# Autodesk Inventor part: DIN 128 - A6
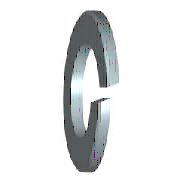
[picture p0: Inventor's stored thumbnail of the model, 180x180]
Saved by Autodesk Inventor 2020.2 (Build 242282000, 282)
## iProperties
Manager: www.cadconsulting.pl
Company: Fabian Stasiak CAD Consulting
Created: 2010-02
Part Number: DIN 128 - A6
Material: Stal, miękka
Description: Podkładka sprężysta
Document SubType Name: Modeling
Standard: DIN 128
Designer: F.Stasiak
Standard Revision: 1994
Standards Organization: DIN
Language: pl-PL
Size Designation: A6
Categories: <MemberInstance><Categories><Category DisplayName="Mocowania" InternalName="e4da775c-781d-43d5-af7c-5136215cf5a6" Mnemonic="FSTN"><Category DisplayName="Podkład
Density: 1 g/cm^3
Appearance: Metal-Stal
IsCustomPart: 0
Author: F.Stasiak
Subject: Zbiór ćwiczeń. Autodesk Inventor 2020. Kurs podstawowy
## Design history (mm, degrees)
sketch "Sketch1"
  geometry: C1 r 5.9 at (0, 0); C2 r 3.25 at (0, 0); 1 further point
  constraints: 2 centre point, 2 coincident
  dimensions: "d0" = 6.5 diameter of C2 (= SD1); "d1" = 11.8 diameter of C1 (= SD2)
extrude "Body" new body sketch "Sketch1" distance "d2" = 1.3 (= SD); taper "d3" = 0 deg
fillet "Fillet" dims "d13" = 0.3 (= R)
sketch "Sketch2"
  geometry: L1 (0, -3.25)-(0, 3.25) reference; L2 (1.3, 5.9)-(1.3, -5.9) reference; L3 (-1.2, 0)-(7.2, 0) reference; L4 (0, -0.26)-(1.3, 0.491); L5 (0, 0.26)-(1.3, 1.011)
  constraints: 4 end point, 4 point on line, 1 parallel
  dimensions: "d4" = 0.26 distance from line of L3 L4.start (= 0.2 x SD); "d5" = 0.26 distance from line of L3 L5.start (= 0.2 x SD); "d6" = 60 deg angle of L2 L4 (= FAWI)
extrude "Cut" cut sketch "Sketch2" stored distance "d7" = 1.3 (= SD); taper "d8" = 0 deg
workaxis "Work Axis1"
workplane "Work Plane1"
body "Solid1"
other parameters: "SD1" = 6.5 [user parameter; used in 1 equation term], "SD2" = 11.8 [user parameter; used in 1 equation term], "SD" = 1.3 [user parameter; used in 4 equation terms], "FAWI" = 60 deg [user parameter; used in 1 equation term], "d9" = 0, "d10" = 0, "d11" = 0, "d12" = 0, "R" = 0.3 [user parameter; used in 1 equation term], "NND" = 6 [user parameter]
